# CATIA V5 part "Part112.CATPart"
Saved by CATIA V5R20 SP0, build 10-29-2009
Part number: FA 063200-2 - comprimido
Revision: ANY
Definition: UNKNOWN
Nomenclature: FA 063200-2 - comprimido
Source: Unknown
Bounding box of the stored display mesh (mm): x -1.95 to 1.95, y 0 to 5.85, z -1.95 to 1.95
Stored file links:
  C:\Users\Utente\Desktop\IO LAVORO\3D X SITO CF\CUMSA\3D files FA\FA 063212-21\Part112.CATPart

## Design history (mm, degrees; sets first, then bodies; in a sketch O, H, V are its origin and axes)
Body1 "Cortar-Extruir1" (main body)
  Solid1: solid without history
